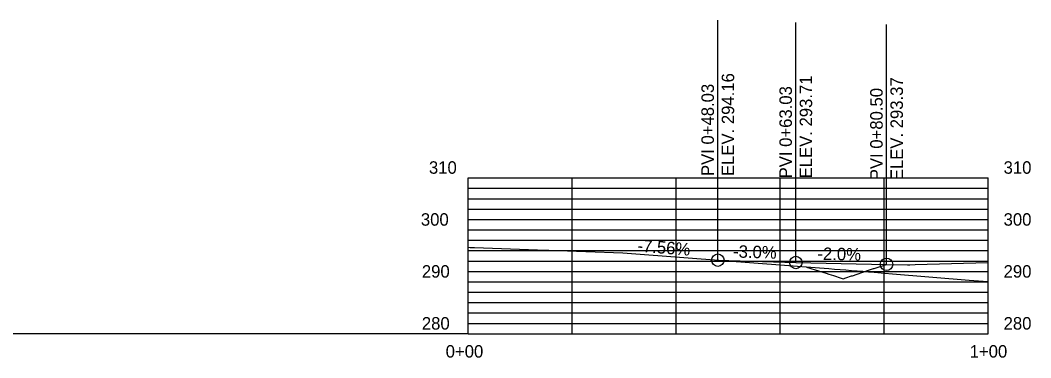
# Model space of a CAD drawing. Extents: x 1709196 to 1718257, y 543790 to 550544.
# Drawn here: x 1710679.2 to 1710873.5, y 544295.7 to 544360.7 of the extents above; entities that cross this region are included whole.
import ezdxf

# ---------------------------------------------------------------- set-up
doc = ezdxf.new("R2010")
doc.units = 0
for name, color, linetype in [('R_Axis', 7, 'Continuous'), ('R_Axis Annot', 7, 'Continuous'), ('R_Exist Surface', 7, 'Continuous'), ('R_Grid', 7, 'Continuous'), ('R_No Plot', 7, 'Continuous'), ('R_Vert Alg', 7, 'Continuous'), ('R_Vert Alg Annot', 7, 'Continuous')]:
    doc.layers.add(name, color=color, linetype=linetype)

msp = doc.modelspace()

# ---------------------------------------------------------------- linework, layer by layer
at = {"layer": 'R_Axis'}
for p, q in [((1710765.3, 544300.33), (1710765.3, 544330.33)), ((1710865.3, 544300.33), (1710865.3, 544330.33)), ((1710765.3, 544300.33), (1710865.3, 544300.33))]:
    msp.add_line(p, q, dxfattribs=at)
at = {"layer": 'R_Exist Surface'}
msp.add_lwpolyline([(1710765.3, 544316.97), (1710765.7, 544316.96), (1710766.56, 544316.92), (1710780.39, 544316.41), (1710780.83, 544316.4), (1710795.04, 544315.88), (1710807.66, 544314.92), (1710820.28, 544313.97), (1710832.9, 544313.01), (1710834.7, 544312.88), (1710835.79, 544312.79), (1710836.88, 544312.71), (1710837.97, 544312.62), (1710839.06, 544312.53), (1710840.15, 544312.45), (1710841.25, 544312.36), (1710842.34, 544312.26), (1710843.42, 544312.17), (1710845.45, 544312), (1710846.96, 544311.83), (1710861.67, 544310.63), (1710865.29, 544310.38)], dxfattribs=at)
at = {"layer": 'R_Grid'}
for p, q in [((1710765.3, 544330.33), (1710865.3, 544330.33)), ((1710765.3, 544330.33), (1710865.3, 544330.33)), ((1710785.3, 544300.33), (1710785.3, 544330.33)), ((1710805.3, 544300.33), (1710805.3, 544330.33)), ((1710825.3, 544300.33), (1710825.3, 544330.33)), ((1710845.3, 544300.33), (1710845.3, 544330.33)), ((1710765.3, 544328.33), (1710865.3, 544328.33)), ((1710765.3, 544326.33), (1710865.3, 544326.33)), ((1710765.3, 544324.33), (1710865.3, 544324.33)), ((1710765.3, 544322.33), (1710865.3, 544322.33)), ((1710765.3, 544320.33), (1710865.3, 544320.33)), ((1710765.3, 544318.33), (1710865.3, 544318.33)), ((1710765.3, 544316.33), (1710865.3, 544316.33)), ((1710765.3, 544314.33), (1710865.3, 544314.33)), ((1710765.3, 544312.33), (1710865.3, 544312.33)), ((1710765.3, 544310.33), (1710865.3, 544310.33)), ((1710765.3, 544308.33), (1710865.3, 544308.33)), ((1710765.3, 544306.33), (1710865.3, 544306.33)), ((1710765.3, 544304.33), (1710865.3, 544304.33)), ((1710765.3, 544302.33), (1710865.3, 544302.33))]:
    msp.add_line(p, q, dxfattribs=at)
at = {"layer": 'R_No Plot'}
msp.add_line((1710765.3, 544300.33), (1709196.12, 544300.33), dxfattribs=at)
at = {"layer": 'R_Vert Alg'}
for p, q in [((1710813.33, 544314.49), (1710828.33, 544314.04)), ((1710828.33, 544314.04), (1710845.79, 544313.69))]:
    msp.add_line(p, q, dxfattribs=at)
msp.add_lwpolyline([(1710830.4, 544313.16), (1710832.06, 544312.63), (1710834.18, 544311.96), (1710834.7, 544311.8), (1710835.58, 544311.52), (1710835.79, 544311.45), (1710836.88, 544311.1), (1710837.44, 544310.92), (1710837.97, 544311.09), (1710839.06, 544311.45), (1710839.21, 544311.5), (1710840.15, 544311.81), (1710841.25, 544312.18), (1710842.34, 544312.54), (1710843.3, 544312.86), (1710843.42, 544312.9), (1710845.79, 544313.69), (1710845.79, 544313.69), (1710849.79, 544313.61), (1710849.79, 544313.61), (1710850.21, 544313.61), (1710850.21, 544313.61), (1710850.21, 544313.61), (1710850.29, 544313.61), (1710850.29, 544313.61), (1710851.29, 544313.63), (1710865.29, 544314.05), (1710865.29, 544314.05), (1710865.29, 544314.05)], dxfattribs=at)
at = {"layer": 'R_Vert Alg Annot'}
for p, q in [((1710813.33, 544329.49), (1710813.33, 544360.69)), ((1710828.33, 544329.04), (1710828.33, 544360.24)), ((1710845.79, 544328.69), (1710845.79, 544359.89)), ((1710813.33, 544314.49), (1710813.33, 544329.49)), ((1710828.33, 544314.04), (1710828.33, 544329.04)), ((1710845.79, 544313.69), (1710845.79, 544328.69))]:
    msp.add_line(p, q, dxfattribs=at)
for centre in [(1710813.33, 544314.49), (1710828.33, 544314.04), (1710845.79, 544313.69)]:
    msp.add_circle(centre, 1.2, dxfattribs=at)

# ---------------------------------------------------------------- texts
at = {"layer": 'R_Axis Annot'}
for s, height, p in [('310', 2.4, (1710757.78, 544331.13)), ('310', 2.4, (1710757.78, 544331.13)), ('310', 2.4, (1710868.3, 544331.13)), ('310', 2.4, (1710868.3, 544331.13)), ('300', 2.4, (1710756.23, 544321.13)), ('300', 2.4, (1710868.3, 544321.13)), ('290', 2.4, (1710756.42, 544311.13)), ('290', 2.4, (1710868.3, 544311.13)), ('280', 2.4, (1710756.42, 544301.13)), ('280', 2.4, (1710868.3, 544301.13)), ('-', 0.0001, (1710765.3, 544300.33)), ('0+00', 2.4, (1710761, 544295.73)), ('1+00', 2.4, (1710861.77, 544295.73))]:
    msp.add_text(s, height=height, dxfattribs=at).set_placement(p)
at = {"layer": 'R_Vert Alg Annot'}
for s, rotation, p in [('ELEV. 294.16', 90, (1710816.48, 544330.69)), ('PVI 0+48.03', 90, (1710812.58, 544330.69)), ('ELEV. 293.71', 90, (1710831.48, 544330.24)), ('ELEV. 293.37', 90, (1710848.94, 544329.89)), ('PVI 0+63.03', 90, (1710827.58, 544330.24)), ('PVI 0+80.50', 90, (1710845.04, 544329.89)), ('-7.56%', 355.6773, (1710797.81, 544316.12)), ('-3.0%', 358.2816, (1710816.24, 544315.01)), ('-2.0%', 358.8542, (1710832.47, 544314.56))]:
    msp.add_text(s, height=2.4, rotation=rotation, dxfattribs=at).set_placement(p)

doc.saveas('drawing.dxf')
